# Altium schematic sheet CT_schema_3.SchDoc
size 421 x 246 mm
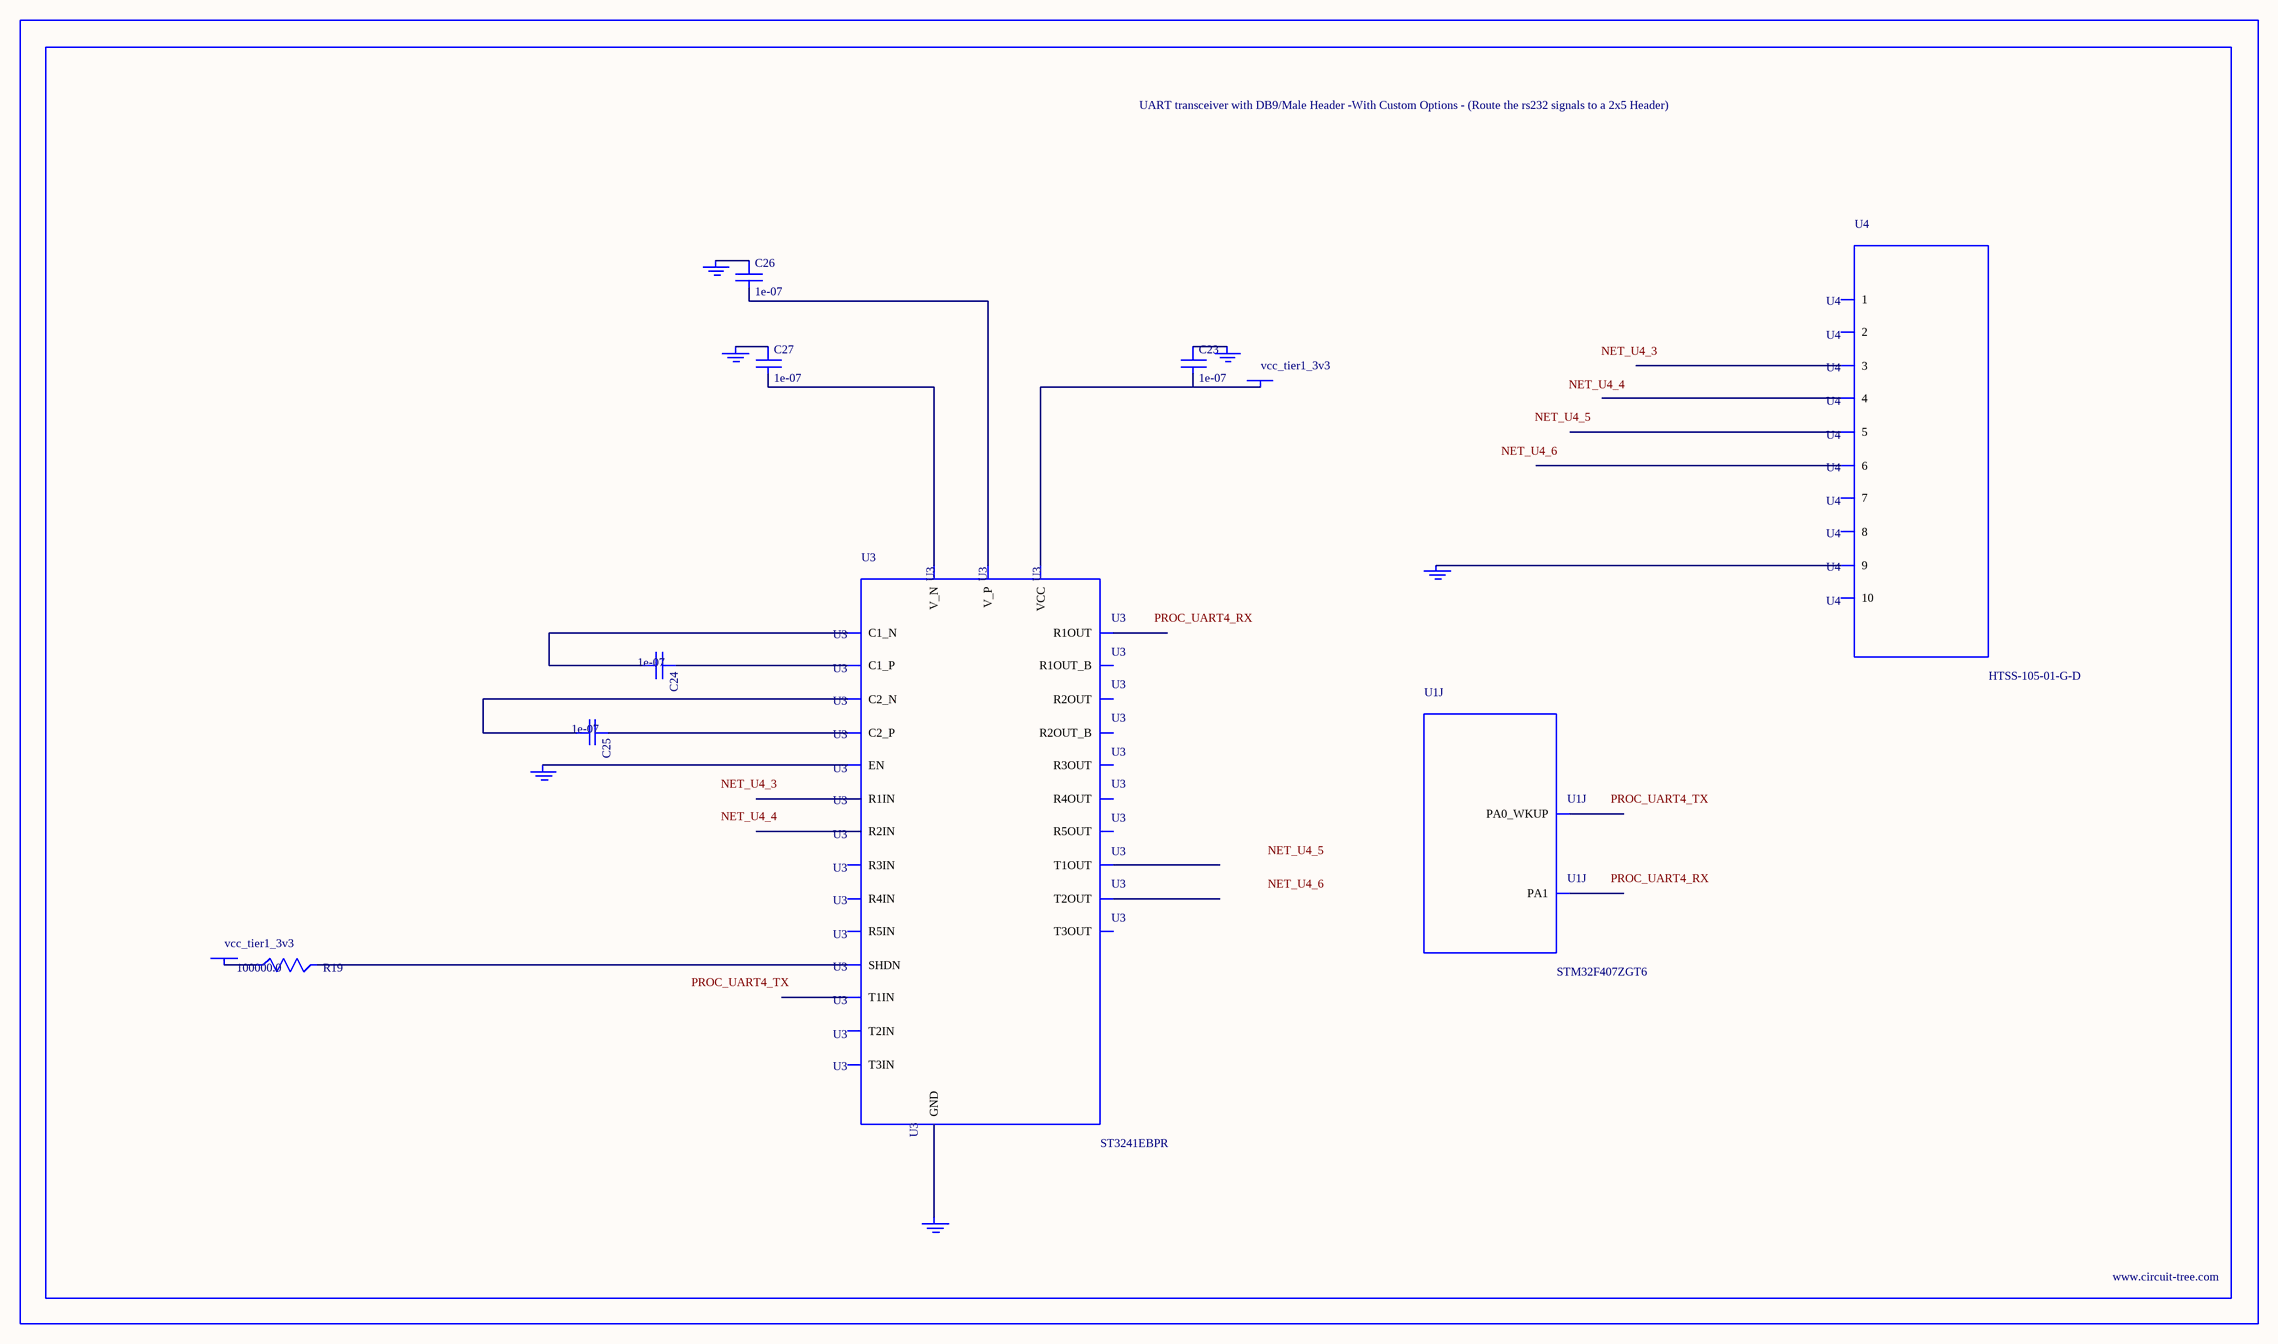
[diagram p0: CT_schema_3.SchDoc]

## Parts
BORDER2  (no value)
C23  1e-07  [C0402]
C24  1e-07  [C0402]
C25  1e-07  [C0402]
C26  1e-07  [C0402]
C27  1e-07  [C0402]
GND_INSTANCE_2_0  (no value)
GND_INSTANCE_2_1  (no value)
GND_INSTANCE_2_2  (no value)
GND_INSTANCE_2_3  (no value)
GND_INSTANCE_2_4  (no value)
GND_INSTANCE_2_5  (no value)
POWER_INSTANCE_2_0  vcc_tier1_3v3
POWER_INSTANCE_2_1  vcc_tier1_3v3
R19  100000.0  [R0603]
U1  STM32F407ZGT6  [LQFP144]  (part J of 11)
U3  ST3241EBPR  [SSOP-28]
U4  HTSS-105-01-G-D  [HTSS-105-01-G-D]

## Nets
NetC23_1: C23.1 GND_INSTANCE_2_2.0(GND)
NetC23_2: C23.2 POWER_INSTANCE_2_1.0(PWR) U3.26(VCC)
NetC24_1: C24.1 U3.28(C1_P)
NetC24_2: C24.2 U3.24(C1_N)
NetC25_1: C25.1 U3.1(C2_P)
NetC25_2: C25.2 U3.2(C2_N)
NetC26_1: C26.1 GND_INSTANCE_2_3.0(GND)
NetC26_2: C26.2 U3.27(V_P)
NetC27_1: C27.1 GND_INSTANCE_2_0.0(GND)
NetC27_2: C27.2 U3.3(V_N)
NetGND_INSTANCE_2_1_0: GND_INSTANCE_2_1.0(GND) U3.23(EN)
NetGND_INSTANCE_2_4_0: GND_INSTANCE_2_4.0(GND) U3.25(GND)
NetGND_INSTANCE_2_5_0: GND_INSTANCE_2_5.0(GND) U4.9
NetPOWER_INSTANCE_2_0_0: POWER_INSTANCE_2_0.0(PWR) R19.1
NetR19_2: R19.2 U3.22(SHDN)

Not connected (* = marked no-connect by the designer): U1 34(PA0_WKUP) 35(PA1); U3 4(R1IN) 5(R2IN) 6(R3IN) 7(R4IN) 8(R5IN) 9(T1OUT) 10(T2OUT) 11(T3OUT) 12(T3IN) 13(T2IN) 14(T1IN) 15(R5OUT) 16(R4OUT) 17(R3OUT) 18(R2OUT) 19(R1OUT) 20(R2OUT_B) 21(R1OUT_B); U4 1 2 3 4 5 6 7 8 10

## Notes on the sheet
- Labels drawn without touching a wire or pin: NET_U4_3, NET_U4_4, NET_U4_5, NET_U4_6, PROC_UART4_RX, PROC_UART4_TX

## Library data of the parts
BORDER2 = BORDER_PAGE2
C23-C27 = C0402C104K3RACTU
GND_INSTANCE_2_0-GND_INSTANCE_2_5 = GND
POWER_INSTANCE_2_0 POWER_INSTANCE_2_1 = PWR
R19 = RC0603JR-07100KL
